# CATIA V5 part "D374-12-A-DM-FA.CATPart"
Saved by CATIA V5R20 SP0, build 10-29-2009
Part number: D374-12-A-DM-FA
Bounding box of the stored display mesh (mm): x -14 to 0.35, y -6 to 6, z -6 to 6
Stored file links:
  C:\Users\Utente\Desktop\IO LAVORO\3D X SITO CF\X SITO\PLASTICA\D374\D374-12-A-DM-FA.CATPart
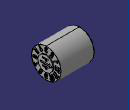
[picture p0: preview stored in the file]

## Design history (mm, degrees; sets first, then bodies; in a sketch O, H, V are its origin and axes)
Set1
  DatumSurface1 to DatumSurface222 "D374-12-A-DM-FA"
Body1 (main body)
